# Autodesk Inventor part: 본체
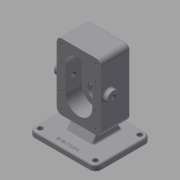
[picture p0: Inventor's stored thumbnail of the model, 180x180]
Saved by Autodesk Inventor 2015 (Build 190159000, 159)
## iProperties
Created: 2020-04
Part Number: 본체
Material: 일반
Document SubType Name: Modeling
Designer: CAD02
Density: 1 g/cm^3
Appearance: 기본값
Mass: 544.054 g
Surface Area: 831.041 cm^2
Volume: 544.054 cm^3
Author: CAD02
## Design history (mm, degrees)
sketch "스케치4"
  geometry: L1 (-24, 44.641)-(24, 44.641) reference; L2 (24, 44.641)-(24, 10) reference; L3 (24, 10)-(60, 10) reference; L4 (60, 10)-(60, 0) reference; L5 (60, 0)-(-60, 0) reference; L6 (-60, 0)-(-60, 10) reference; L7 (-60, 10)-(-24, 10) reference; L8 (-24, 10)-(-24, 44.641) reference; L9 (40, 150)-(-40, 150); L10 (-40, 150)-(-40, 30); L11 (-40, 30)-(40, 30); L12 (40, 30)-(40, 150); 3 further points
  constraints: 8 end point, 2 midpoint, 2 parallel, 1 horizontal, 1 perpendicular, 1 vertical alignment
  dimensions: "d19" = 150 distance between parallel lines of L5 L9; "d20" = 120 distance of L11.end L9.start; "d21" = 80 distance of L9.start L9.end
extrude "돌출3" join sketch "스케치4" stored distance "d22" = 53; taper "d23" = 0 deg
sketch "스케치5"
  geometry: L1 (0, 112)-(0, 68); L2 (24, 112)-(24, 68); L3 (-24, 68)-(-24, 112); L4 (-50, 0)-(50, 0) reference; A1 r 24 centre (0, 112) between (24, 112) and (-24, 112); A2 r 24 centre (0, 68) between (-24, 68) and (24, 68); 2 further points
  constraints: 8 end point, 4 point on circle, 4 tangent, 2 centre point, 1 midpoint, 1 parallel, 1 vertical
  dimensions: "d24" = 92 dimension on A2 A1; "d25" = 44 distance of L1.end L1.start; "d26" = 90 distance from line of L4 point (0, 90)
extrude "돌출4" cut sketch "스케치5" distance "d27" = 29; taper "d28" = 0 deg
sketch "스케치6"
  geometry: C1 r 12.5 at (0, 112); C2 r 12.5 at (0, 68); A1 r 24 centre (0, 112) between (24, 112) and (-24, 112) reference; A2 r 24 centre (0, 68) between (-24, 68) and (24, 68) reference; 1 further point
  constraints: 2 centre point, 2 coincident
  dimensions: "d29" = 25 diameter of C1; "d30" = 25 diameter of C2
extrude "돌출5" cut sketch "스케치6" distance "d31" = 15; taper "d32" = 0 deg
sketch "스케치7"
  geometry: C1 r 19 at (0, -112); A1 r 24 centre (0, -112) between (-24, -112) and (24, -112) reference; 1 further point
  constraints: 1 centre point, 1 coincident
  dimensions: "d33" = 38 diameter of C1
extrude "돌출6" join sketch "스케치7" distance "d34" = 17; taper "d35" = 0 deg
sketch "스케치8"
  geometry: C1 r 19 at (0, 0) reference; C2 r 14 at (0, 0); 1 further point
  constraints: 1 centre point, 1 coincident
  dimensions: "d36" = 28 diameter of C2
extrude "돌출7" cut sketch "스케치8" distance "d37" = 7.3; taper "d38" = 0 deg
sketch "스케치9"
  geometry: C1 r 14 at (0, 0) reference; C2 r 8.5 at (0, 0); 1 further point
  constraints: 1 centre point, 1 coincident
  dimensions: "d39" = 17 diameter of C2
extrude "돌출8" cut sketch "스케치9" stored distance "d40" = 7.3; taper "d41" = 0 deg
chamfer "모따기1" distance "d42" = 0.7; stored, may be unused: second distance "d43" = 2, angle "d44" = 30 deg
fillet "모깎기2" dims "d45" = 0.5
node "작업 평면3"
sketch "스케치11"
  geometry: L1 (-40, 30)-(40, 30) reference; L2 (-31, 141)-(31, 141); L3 (31, 141)-(31, 39); L4 (31, 39)-(-31, 39); L5 (-31, 39)-(-31, 141); L6 (-40, 150)-(40, 150) reference; L7 (0, 150)-(0, 30); L8 (-31, 112)-(31, 112); L9 (-31, 90)-(31, 90); L10 (-31, 68)-(31, 68); L11 (40, 150)-(-40, 150) reference; 12 further points
  constraints: 16 end point, 8 coincident, 7 midpoint, 4 horizontal, 4 point on line, 2 parallel, 1 horizontal alignment, 1 perpendicular, 1 vertical alignment
  dimensions: "d54" = 62 distance of L2.start L2.end; "d55" = 102 distance of L4.end L2.start; "d56" = 29 distance between parallel lines of L8 L2; "d57" = 44 distance between parallel lines of L10 L8
hole "구멍2" sketch "스케치11" at (-31, 141), (-31, 112), (-31, 68), (-31, 39), (31, 39), (31, 68), (31, 112), (31, 141) diameter "d58" = 4.134; stored, may be unused: countersink angle "d62" = 90 deg, drill point angle "d64" = 118 deg; dims "d59" = 10, "d60" = 4, "d61" = 2, "d63" = 12
chamfer "모따기2" distance "d65" = 1; stored, may be unused: second distance "d66" = 2, angle "d67" = 30 deg
fillet "모깎기7" dims "d68" = 3
fillet "모깎기9" dims "d70" = 9
fillet "모깎기10" dims "d71" = 3
sketch "스케치12"
  geometry: L1 (102, 0)-(0, 0) reference; C1 r 11 at (51, 14); 1 further point
  constraints: 1 centre point
  dimensions: "d72" = 22 diameter of C1; "d73" = 14 distance from line of L1 C1.centre
extrude "돌출9" join sketch "스케치12" distance "d74" = 8; taper "d75" = 0 deg
fillet "모깎기11" dims "d76" = 3
sketch "스케치13"
  geometry: L1 (102, 0)-(0, 0) reference; C1 r 11 at (51, 14); 1 further point
  constraints: 1 centre point
  dimensions: "d77" = 22 diameter of C1; "d78" = 14 distance from line of L1 C1.centre
extrude "돌출10" join sketch "스케치13" distance "d79" = 8; taper "d80" = 0 deg
fillet "모깎기12" dims "d81" = 3
sketch "스케치14"
  geometry: C1 r 11 at (0, 0) reference; 1 further point
hole "구멍3" sketch "스케치14" at (0, 0) diameter "d82" = 8.376; stored, may be unused: countersink angle "d86" = 90 deg, drill point angle "d88" = 118 deg; dims "d83" = 20, "d84" = 4, "d85" = 2, "d87" = 27.3
sketch "스케치15"
  geometry: C1 r 11 at (0, 0) reference; 1 further point
hole "구멍4" sketch "스케치15" at (0, 0) diameter "d89" = 8.376; stored, may be unused: countersink angle "d93" = 90 deg, drill point angle "d95" = 118 deg; dims "d90" = 20, "d91" = 4, "d92" = 2, "d94" = 27.3
node "작업 평면4"
sketch "스케치16"
  geometry: L1 (91, -30)-(-29, -30); L2 (-29, -30)-(-29, 70); L3 (-29, 70)-(91, 70); L4 (91, 70)-(91, -30); L5 (91, -30)-(-29, 70); L6 (-29, -30)-(91, 70); L7 (50, 70)-(12, 70) reference; 3 further points
  constraints: 12 end point, 4 midpoint, 2 parallel, 1 horizontal, 1 perpendicular, 1 vertical alignment
  dimensions: "d97" = 120 distance of L2.end L3.end; "d98" = 100 distance of L1.end L2.end
extrude "돌출11" join sketch "스케치16" distance "d99" = 10; taper "d100" = 0 deg
sketch "스케치17"
  geometry: L1 (-29, -30)-(91, -30) reference; L2 (91, 70)-(-29, 70) reference; L3 (55, 0)-(7, 0); L4 (7, 0)-(7, 53); L5 (7, 53)-(55, 53); L6 (55, 53)-(55, 0); L7 (55, 0)-(7, 53); L8 (7, 0)-(55, 53); 4 further points
  constraints: 12 end point, 4 midpoint, 2 parallel, 1 horizontal, 1 perpendicular, 1 vertical alignment
  dimensions: "d101" = 48 distance of L3.start L3.end; "d102" = 53 distance of L5.end L3.start; "d103" = 17 distance between parallel lines of L5 L2
extrude "돌출12" new body sketch "스케치17" distance "d104" = 30; taper "d105" = 0 deg
feature "면 기울기3" dims angle "d106" = 30 deg
feature "결합1"
  node "솔리드2"
fillet "모깎기13" dims "d107" = 10
fillet "모깎기14" dims "d108" = 3
sketch "스케치18"
  geometry: A1 r 7 centre (-19, 60) between (-19, 67) and (-26, 60) reference; A2 r 7 centre (-19, -20) between (-26, -20) and (-19, -27) reference; A3 r 7 centre (81, -20) between (81, -27) and (88, -20) reference; A4 r 7 centre (81, 60) between (88, 60) and (81, 67) reference; 1 further point
hole "구멍5" sketch "스케치18" at (81, 60), (-19, 60), (-19, -20), (81, -20) diameter "d109" = 9; stored, may be unused: countersink angle "d113" = 90 deg, drill point angle "d115" = 118 deg; dims "d110" = 20, "d111" = 4, "d112" = 2, "d114" = 27.3
sketch "스케치19"
  geometry: L1 (-29, 60)-(-29, -20) reference; L2 (-19, -30)-(81, -30) reference; 2 further points
  constraints: 1 other
  dimensions: "d116" = 60 distance from line of L1 point (31, -20); "d117" = 10 distance from line of L2 point (31, -20)
feature "엠보싱2" sketch "스케치19" dims "d118" = 0.5, "d119" = 0
fillet "모깎기15" dims "d120" = 3
fillet "모깎기16" dims "d121" = 3
node "솔리드1"
mirror "대칭1"
node "절단 모서리 투영1"
